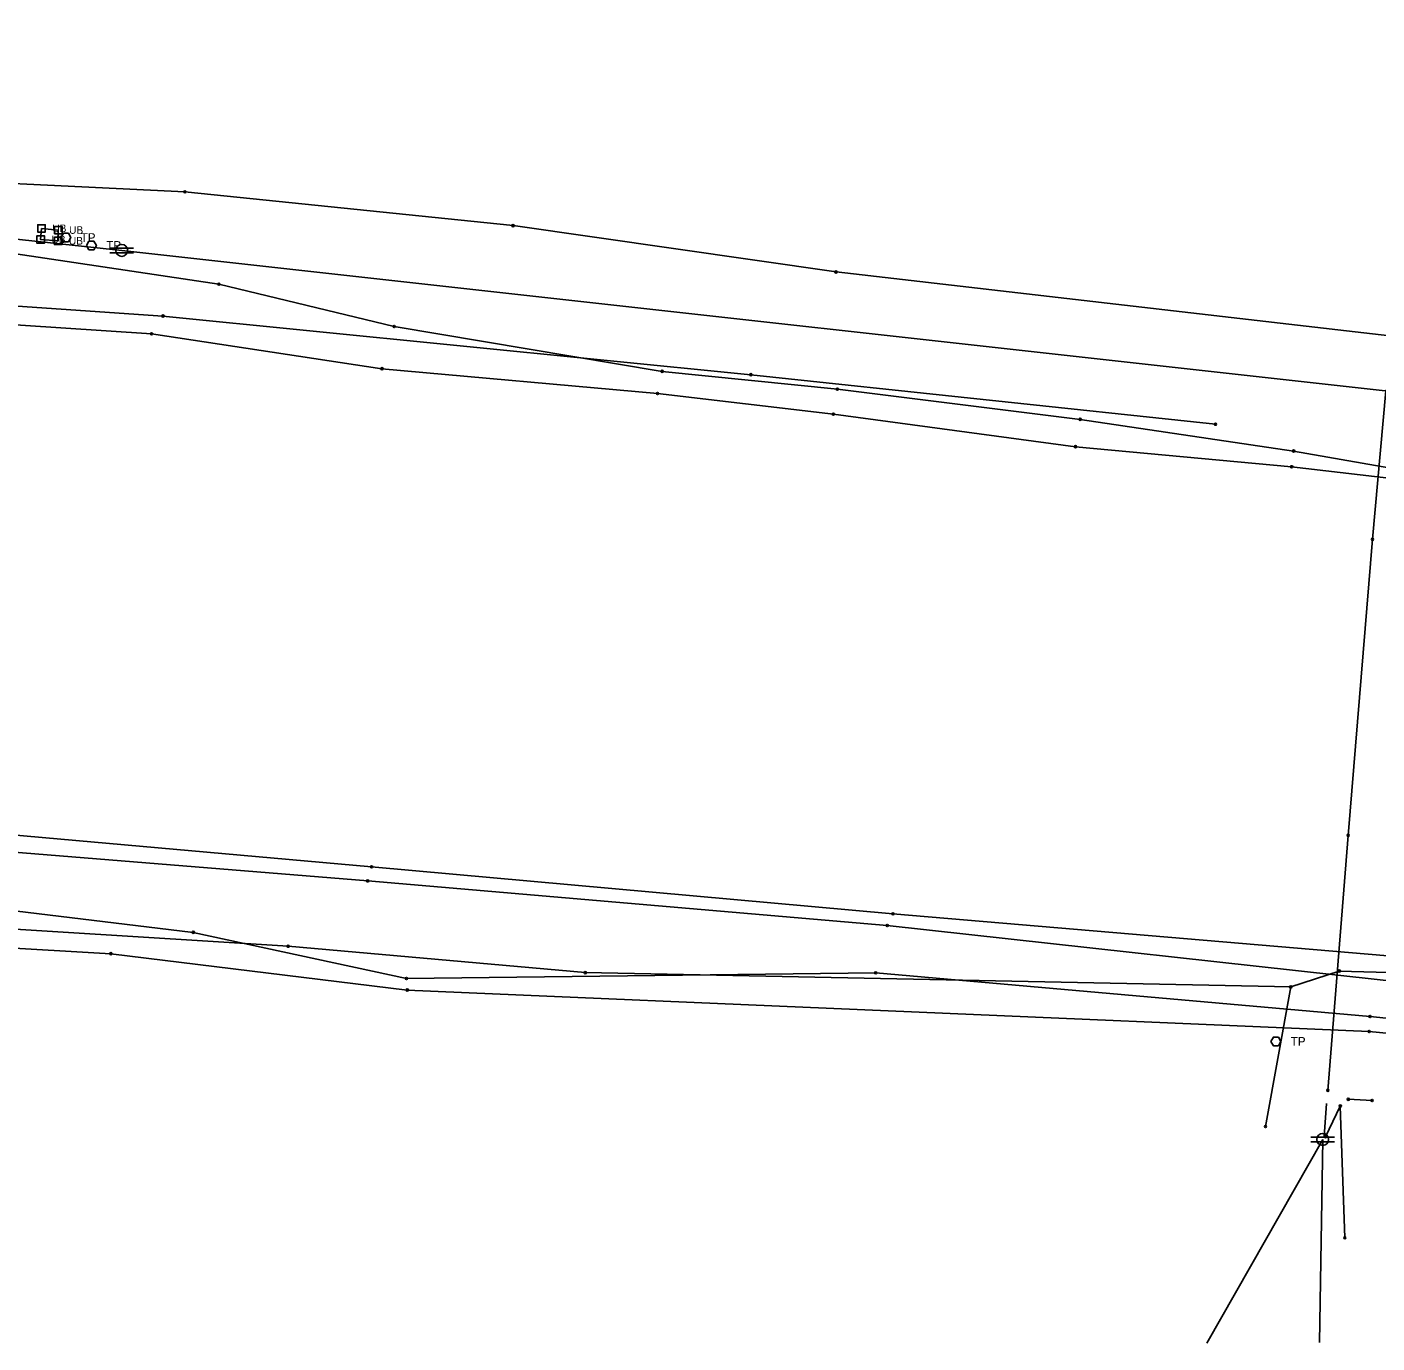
# Model space of a CAD drawing. Extents: x 20500343 to 20505311, y 7953484 to 7954193.
# Drawn here: x 20502176.1 to 20502424.8, y 7953715.9 to 7953958.2 of the extents above; entities that cross this region are included whole.
import ezdxf

# ---------------------------------------------------------------- set-up
doc = ezdxf.new("R2010")
doc.units = 0
for name, color, linetype in [('C-PROP-LINE-LOT', 7, 'Continuous'), ('V-ANNO-BNDY', 7, 'Continuous'), ('V-ANNO-NOTE', 7, 'Continuous'), ('V-CTRL-HVPT', 7, 'Continuous'), ('V-MON-FND', 7, 'Continuous'), ('V-SITE-FENC', 7, 'Continuous')]:
    doc.layers.add(name, color=color, linetype=linetype)

msp = doc.modelspace()

# ---------------------------------------------------------------- linework, layer by layer
at = {"layer": 'C-PROP-LINE-LOT'}
for points in [[(20501786.53, 7953958.21), (20501802.89, 7953943.86), (20501839.77, 7953931.6), (20501880.96, 7953927.96), (20502018.29, 7953917.03), (20502077.19, 7953911.09), (20502142.41, 7953905.45), (20502199.08, 7953901.71), (20502241.51, 7953895.28), (20502292.25, 7953890.73), (20502324.65, 7953886.92), (20502369.24, 7953880.93), (20502409.05, 7953877.23), (20502443.31, 7953873.2), (20502481.36, 7953863.28), (20502512.4, 7953858.05), (20502594.55, 7953857.22)], [(20501786.53, 7953958.21), (20501798.37, 7953955.39), (20501845.31, 7953947.9), (20501861.48, 7953946.79), (20501912.59, 7953941.56), (20501926.87, 7953941.71), (20502019.52, 7953933.84), (20502080.36, 7953927.46), (20502107.02, 7953924.08), (20502144.15, 7953919.15), (20502174.11, 7953916.47), (20502211.46, 7953910.85), (20502243.75, 7953903.07), (20502293.11, 7953894.8), (20502325.39, 7953891.51), (20502370.1, 7953885.96), (20502409.42, 7953880.13), (20502443.48, 7953874.15), (20502481.41, 7953864.06), (20502512.42, 7953858.66), (20502594.72, 7953856.58)], [(20501927.57, 7953950.71), (20501980.32, 7953946.58), (20502008.33, 7953945.23), (20502082.1, 7953936.78), (20502144.41, 7953930.79), (20502205.22, 7953927.86), (20502265.66, 7953921.64), (20502325.14, 7953913.11), (20502432.98, 7953900.65), (20502447.13, 7953900.6), (20502499.42, 7953893.79), (20502538.42, 7953891.09), (20502589.85, 7953886.97), (20502611.07, 7953885.99)], [(20501941.48, 7953944.15), (20502193.58, 7953917.07), (20502451.16, 7953888.46), (20502584.33, 7953884.2), (20502691.76, 7953878.47)], [(20501804.54, 7953940.37), (20502005.09, 7953923.1), (20502111.03, 7953911.19), (20502201.18, 7953904.98), (20502309.45, 7953894.18), (20502395.03, 7953885.06)], [(20502415.71, 7953762.4), (20502419.47, 7953809.35), (20502423.95, 7953863.88), (20502426.43, 7953891.24), (20502433.02, 7953899.45), (20502447.47, 7953898.8), (20502500.14, 7953892.2), (20502538.94, 7953889.66), (20502589.43, 7953885.63), (20502611.13, 7953884.64)], [(20501822.69, 7953839.61), (20501870.85, 7953834.49), (20501955.49, 7953824.45), (20502075.53, 7953814.96), (20502170.68, 7953806.48), (20502238.89, 7953800.97), (20502334.58, 7953792.75), (20502432.59, 7953781.98), (20502508.31, 7953776.06), (20502531.87, 7953776.49), (20502581.28, 7953773.17)], [(20501871.18, 7953838.12), (20501950.16, 7953828.62), (20502076.03, 7953818.34), (20502154.77, 7953811.13), (20502239.61, 7953803.57), (20502335.63, 7953794.91), (20502433.27, 7953786.61), (20502509.73, 7953784.12), (20502531.75, 7953782.62), (20502583.58, 7953780.86)], [(20501766.01, 7953834.76), (20501821.75, 7953833.43), (20501869.61, 7953826.07), (20501921.27, 7953820.74), (20501975.38, 7953813.59), (20502027.18, 7953809.28), (20502096.84, 7953802.19), (20502149.48, 7953798.41), (20502206.76, 7953791.49), (20502246.02, 7953783), (20502332.45, 7953784.05), (20502423.49, 7953775.99), (20502457.77, 7953772.43), (20502468.01, 7953774.31), (20502490.69, 7953772.12), (20502532.01, 7953768.89), (20502567.5, 7953767.25)], [(20501765.8, 7953831.13), (20501934, 7953813.62), (20501986.76, 7953807.7), (20502096.89, 7953796.9), (20502224.25, 7953788.94), (20502278.96, 7953784.08), (20502408.88, 7953781.44), (20502417.83, 7953784.37), (20502465.46, 7953783.06), (20502531.65, 7953780.57), (20502583.55, 7953776.2)], [(20501923.78, 7953810.45), (20501976.29, 7953805.33), (20502027.19, 7953800.79), (20502097.04, 7953794.03), (20502148.61, 7953790.06), (20502191.57, 7953787.56), (20502246.17, 7953780.88), (20502423.34, 7953773.23), (20502457.56, 7953769.95), (20502471.39, 7953769.52), (20502491.18, 7953768.99), (20502531.55, 7953766.92), (20502567.17, 7953761.38)], [(20502408.88, 7953781.44), (20502404.25, 7953755.74)], [(20502415.49, 7953760), (20502415.02, 7953753.91)], [(20502415.28, 7953753.84), (20502418.01, 7953759.51)], [(20502418.86, 7953735.25), (20502418.01, 7953759.51)], [(20502423.87, 7953760.54), (20502419.49, 7953760.75)], [(20502414.77, 7953753.36), (20502393.42, 7953715.88)], [(20502414.77, 7953753.36), (20502414.17, 7953716)]]:
    msp.add_lwpolyline(points, dxfattribs=at)
at = {"layer": 'V-ANNO-BNDY'}
msp.add_line((20502414.77, 7953753.36), (20502414.77, 7953753.36), dxfattribs=at)
at = {"layer": 'V-ANNO-NOTE'}
for centre in [(20502205.22, 7953927.86), (20502265.66, 7953921.64), (20502325.14, 7953913.11), (20502211.46, 7953910.85), (20502201.18, 7953904.98), (20502243.75, 7953903.07), (20502199.08, 7953901.71), (20502241.51, 7953895.28), (20502293.11, 7953894.8), (20502309.45, 7953894.18), (20502292.25, 7953890.73), (20502325.39, 7953891.51), (20502324.65, 7953886.92), (20502370.1, 7953885.96), (20502395.03, 7953885.06), (20502369.24, 7953880.93), (20502409.42, 7953880.13), (20502409.05, 7953877.23), (20502423.95, 7953863.88), (20502419.47, 7953809.35), (20502239.61, 7953803.57), (20502238.89, 7953800.97), (20502335.63, 7953794.91), (20502206.76, 7953791.49), (20502334.58, 7953792.75), (20502224.25, 7953788.94), (20502191.57, 7953787.56), (20502278.96, 7953784.08), (20502332.45, 7953784.05), (20502417.83, 7953784.37), (20502246.02, 7953783), (20502246.17, 7953780.88), (20502408.88, 7953781.44), (20502408.88, 7953781.44), (20502423.49, 7953775.99), (20502423.34, 7953773.23), (20502415.71, 7953762.4), (20502418.01, 7953759.51), (20502418.01, 7953759.51), (20502419.49, 7953760.75), (20502423.87, 7953760.54), (20502404.25, 7953755.74), (20502415.28, 7953753.84), (20502418.86, 7953735.25)]:
    msp.add_circle(centre, 0.2, dxfattribs=at)
at = {"layer": 'V-CTRL-HVPT'}
for p, q in [((20502191.38, 7953917.51), (20502195.78, 7953917.51)), ((20502191.38, 7953916.63), (20502195.78, 7953916.63)), ((20502412.57, 7953753.8), (20502416.97, 7953753.8)), ((20502412.57, 7953752.92), (20502416.97, 7953752.92))]:
    msp.add_line(p, q, dxfattribs=at)
for centre in [(20502193.58, 7953917.07), (20502414.77, 7953753.36)]:
    msp.add_circle(centre, 1.1, dxfattribs=at)
at = {"layer": 'V-MON-FND'}
msp.add_lwpolyline([(20502178.81, 7953921.12), (20502181.9, 7953920.81), (20502181.87, 7953918.82), (20502178.65, 7953919.07)], close=True, dxfattribs=at)
msp.add_lwpolyline([(20502178.81, 7953921.12), (20502181.9, 7953920.81), (20502181.87, 7953918.82), (20502178.65, 7953919.07)], close=True, dxfattribs=at)
for points in [[(20502182.38, 7953919.44), (20502182.83, 7953920.23), (20502183.75, 7953920.23), (20502184.2, 7953919.44), (20502183.75, 7953918.64), (20502182.83, 7953918.64), (20502182.38, 7953919.44)], [(20502187.1, 7953917.98), (20502187.55, 7953918.77), (20502188.47, 7953918.77), (20502188.92, 7953917.98), (20502188.47, 7953917.18), (20502187.55, 7953917.18), (20502187.1, 7953917.98)], [(20502405.24, 7953771.42), (20502405.69, 7953772.21), (20502406.61, 7953772.21), (20502407.06, 7953771.42), (20502406.61, 7953770.63), (20502405.69, 7953770.63), (20502405.24, 7953771.42)]]:
    msp.add_lwpolyline(points, dxfattribs=at)
at = {"layer": 'V-SITE-FENC'}
for points in [[(20502178.81, 7953920.43), (20502178.81, 7953920.43), (20502179.5, 7953920.43), (20502179.5, 7953921.8), (20502178.12, 7953921.8), (20502178.12, 7953920.43), (20502178.81, 7953920.43)], [(20502181.9, 7953920.13), (20502181.9, 7953920.13), (20502182.59, 7953920.13), (20502182.59, 7953921.5), (20502181.21, 7953921.5), (20502181.21, 7953920.13), (20502181.9, 7953920.13)], [(20502178.65, 7953918.39), (20502178.65, 7953918.39), (20502179.34, 7953918.39), (20502179.34, 7953919.76), (20502177.96, 7953919.76), (20502177.96, 7953918.39), (20502178.65, 7953918.39)], [(20502181.87, 7953918.13), (20502181.87, 7953918.13), (20502182.56, 7953918.13), (20502182.56, 7953919.5), (20502181.18, 7953919.5), (20502181.18, 7953918.13), (20502181.87, 7953918.13)]]:
    msp.add_lwpolyline(points, dxfattribs=at)

# ---------------------------------------------------------------- texts
at = {"layer": 'V-MON-FND'}
for p in [(20502186.03, 7953918.64), (20502190.75, 7953917.18), (20502408.89, 7953770.62)]:
    msp.add_text('TP', height=1.599, dxfattribs=at).set_placement(p)
at = {"layer": 'V-SITE-FENC'}
for p in [(20502180.8, 7953920.44), (20502183.89, 7953920.13), (20502180.64, 7953918.39), (20502183.86, 7953918.14)]:
    msp.add_text('UB', height=1.399, dxfattribs=at).set_placement(p)

doc.saveas('drawing.dxf')
